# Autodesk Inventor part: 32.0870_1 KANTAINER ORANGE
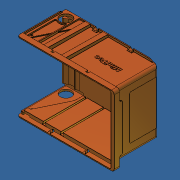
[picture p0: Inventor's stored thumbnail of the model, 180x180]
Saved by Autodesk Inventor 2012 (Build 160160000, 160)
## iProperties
Created: 2013-07
Part Number: 32.0870_1 KANTAINER ORANGE
Material: Polypropylene
Document SubType Name: Modeling
Designer: Admin
Density: 0.899 g/cm^3
Mass: 123.05 g
Surface Area: 1354.89 cm^2
Volume: 136.875 cm^3
Author: Admin
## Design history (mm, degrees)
node "001049341"
node "Volumenkörper1"
node "Base1"
